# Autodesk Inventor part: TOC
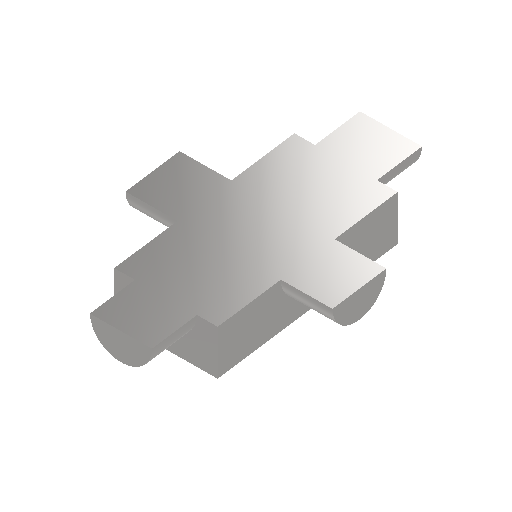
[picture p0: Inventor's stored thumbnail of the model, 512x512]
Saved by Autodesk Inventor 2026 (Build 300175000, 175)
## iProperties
Created: 2004-10
Part Number: TOC
Document SubType Name: Modeling
Designer: Lars Bertram Pedersen
Manufacturer: Standard
Standards Organization: Custom
Material: Steel, Mild
Density: 7.85 g/cm^3
Appearance: Semi-Polished
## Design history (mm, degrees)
sketch "Sketch1"
  geometry: L1 (-50, 0)-(50, 0); L2 (50, 0)-(50, 25); L3 (50, 25)-(-50, 25); L4 (-50, 25)-(-50, 0); 2 further points
  constraints: 8 end point, 2 parallel, 1 coincident, 1 horizontal, 1 midpoint, 1 perpendicular
  dimensions: "d0" = 100 distance of L1.start L1.end; "d1" = 25 distance of L3.end L1.start
extrude "Extrusion1" new body sketch "Sketch1" distance "d2" = 50; taper "d3" = 0 deg
workplane "Work Plane1"
sketch "Sketch2"
  geometry: L1 (-15, 25)-(15, 25); L2 (50, 25)-(-50, 25) reference; A1 r 15 centre (0, 25) between (-15, 25) and (15, 25); 1 further point
  constraints: 2 end point, 2 midpoint, 2 point on circle, 1 centre point, 1 coincident, 1 collinear
  dimensions: "d5" = 15 radius of A1
extrude "Extrusion2" join sketch "Sketch2" distance "d6" = 100; taper "d7" = 0 deg
workplane "Work Plane2"
sketch "Sketch3"
  geometry: L1 (0, -65)-(0, -35); L2 (0, 0)-(0, -25) reference; A1 r 15 centre (0, -50) between (0, -35) and (0, -65); 1 further point
  constraints: 2 end point, 2 point on circle, 1 centre point, 1 coincident, 1 collinear, 1 midpoint, 1 other
  dimensions: "d9" = 15 radius of A1
extrude "Extrusion3" join sketch "Sketch3" stored distance "d10" = 150; taper "d11" = 0 deg
workplane "Work Plane4"
body "Solid1"
other parameters: "d4" = 25
